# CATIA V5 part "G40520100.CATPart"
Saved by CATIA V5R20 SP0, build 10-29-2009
Part number: G40520100
Revision: 6
Definition: design
Nomenclature: G40520100
Source: made
Description: NOT SPECIFIED
Bounding box of the stored display mesh (mm): x -50 to 50, y -10 to 10, z -20 to 0
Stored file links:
  C:\Users\Raffaele\Desktop\3D X SITO CF\BOLEX\29-GUIDE STRIP REF 405\G40520100.CATPart
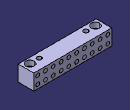
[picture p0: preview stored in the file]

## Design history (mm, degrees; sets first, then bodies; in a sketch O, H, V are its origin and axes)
Body1 "MANIFOLD_SOLID_BREP #3622" (main body)
  Solid1: solid without history
Body2 "MANIFOLD_SOLID_BREP #3760"
  Solid2: solid without history
Body3 "MANIFOLD_SOLID_BREP #3872"
  Solid3: solid without history
Body4 "MANIFOLD_SOLID_BREP #3984"
  Solid4: solid without history
Body5 "MANIFOLD_SOLID_BREP #4096"
  Solid5: solid without history
Body6 "MANIFOLD_SOLID_BREP #4208"
  Solid6: solid without history
Body7 "MANIFOLD_SOLID_BREP #4320"
  Solid7: solid without history
Body8 "MANIFOLD_SOLID_BREP #4432"
  Solid8: solid without history
Body9 "MANIFOLD_SOLID_BREP #4544"
  Solid9: solid without history
Body10 "MANIFOLD_SOLID_BREP #4656"
  Solid10: solid without history
Body11 "MANIFOLD_SOLID_BREP #4768"
  Solid11: solid without history
Body12 "MANIFOLD_SOLID_BREP #4880"
  Solid12: solid without history
Body13 "MANIFOLD_SOLID_BREP #4992"
  Solid13: solid without history
Body14 "MANIFOLD_SOLID_BREP #5104"
  Solid14: solid without history
Body15 "MANIFOLD_SOLID_BREP #5216"
  Solid15: solid without history
Body16 "MANIFOLD_SOLID_BREP #5328"
  Solid16: solid without history
Body17 "MANIFOLD_SOLID_BREP #5440"
  Solid17: solid without history
Body18 "MANIFOLD_SOLID_BREP #5552"
  Solid18: solid without history
Body19 "MANIFOLD_SOLID_BREP #5664"
  Solid19: solid without history
Body20 "MANIFOLD_SOLID_BREP #5776"
  Solid20: solid without history
Body21 "MANIFOLD_SOLID_BREP #5914"
  Solid21: solid without history
Body22 "MANIFOLD_SOLID_BREP #6052"
  Solid22: solid without history
Body23 "MANIFOLD_SOLID_BREP #6190"
  Solid23: solid without history
Body24 "MANIFOLD_SOLID_BREP #6328"
  Solid24: solid without history
Body25 "MANIFOLD_SOLID_BREP #6466"
  Solid25: solid without history
Body26 "MANIFOLD_SOLID_BREP #6604"
  Solid26: solid without history
Body27 "MANIFOLD_SOLID_BREP #6742"
  Solid27: solid without history
Body28 "MANIFOLD_SOLID_BREP #6880"
  Solid28: solid without history
Body29 "MANIFOLD_SOLID_BREP #6992"
  Solid29: solid without history
Body30 "MANIFOLD_SOLID_BREP #7104"
  Solid30: solid without history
